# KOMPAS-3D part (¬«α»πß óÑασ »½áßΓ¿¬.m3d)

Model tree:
1. Эскиз:1
2. Операция выдавливания:1
     Расстояние 1 = 2
3. Эскиз:2
4. Вырезать элемент выдавливания:1
     Расстояние 1 = 2

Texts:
  корпус верх пластик
  Полипропилен  ГОСТ 26996-86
